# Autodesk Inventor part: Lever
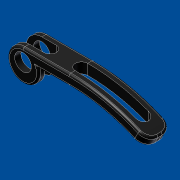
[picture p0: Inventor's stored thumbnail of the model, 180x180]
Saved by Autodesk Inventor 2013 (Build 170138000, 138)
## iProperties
Shininess: 41.0
Length Units: 11269
Angle Units: 11279
Time Units: 11290
Mass Units: 11283
Length Display Precision: 3
Angle Display Precision: 2
Created: 2001-04
Part Number: Lever
Material: Standard
Document SubType Name: Modellieren
Designer: dl
Density: 1 g/cm^3
Density: 0.0
Volumn: 0.0
Area: 0.0
PropertySet Name: Model Information
Control State: 0
Master: False
Checked Out: False
Author: dl
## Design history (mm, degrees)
sketch "Sketch1"
  geometry: L1 (-62.431, -13.947)-(-40.431, -13.947); L2 (-55.36, -18.947)-(-40.431, -18.947); L3 (-2.431, -23.212)-(-40.431, -96.502); A1 r 7.5 centre (-62.431, -21.447) between (-62.431, -13.947) and (-55.36, -18.947); A2 r 82.556 centre (-40.431, -96.502) between (-2.431, -23.212) and (-40.431, -13.947); A3 r 77.556 centre (-40.431, -96.502) between (-4.733, -27.651) and (-40.431, -18.947)
  constraints: 7 end point, 6 point on circle, 3 centre point, 3 tangent, 1 concentric, 1 horizontal, 1 parallel, 1 point on line
  dimensions: "d0" = 7.5 radius of A1; "d3" = 22 distance of L1.start L1.end; "d4" = 60 horizontal distance of L3.start A1.centre; "d5" = 5 distance of A3.start L3.start
extrude "Extrusion1" new body sketch "Sketch1" distance "d6" = 12; taper "d7" = 0 deg
sketch "Sketch2"
  geometry: L1 (0, 0)-(0, -12) reference; L2 (-10, -3)-(10, -3); L3 (10, -3)-(10, -9); L4 (10, -9)-(-10, -9); L5 (-10, -9)-(-10, -3); L6 (7.5, -16)-(-7.5, -12) reference; L7 (0, 0)-(0, -12)
  constraints: 10 end point, 3 equal length, 1 horizontal, 1 perpendicular
  dimensions: "d8" = 6 distance of L4.end L2.start; "d9" = 3 distance between parallel lines of L6 L4; "d10" = 10 distance from line of L2.end L1; "d11" = 20 distance of L2.start L2.end
extrude "Extrusion2" cut sketch "Sketch2" distance "d12" = 30; taper "d13" = 0 deg
sketch "Sketch3"
  geometry: L1 (54, -9)-(19, -9); L2 (19, -9)-(19, -3); L3 (19, -3)-(54, -3); L4 (54, -3)-(54, -9); L5 (7.5, 0)-(-7.5, 0) reference; A1 r 3 centre (7, -6) between (7, -9) and (7, -3) reference
  constraints: 8 end point, 2 parallel, 1 horizontal, 1 perpendicular
  dimensions: "d15" = 6 distance of L1.end L2.end; "d16" = 3 distance between parallel lines of L5 L3; "d17" = 12 distance from line of A1.centre L2; "d18" = 35 distance of L1.start L1.end
extrude "Extrusion3" cut sketch "Sketch3" stored distance "d19" = 30; taper "d20" = 0 deg
body "Solid1"
fillet "Fillet1" dims "d14" = 3
fillet "Fillet2" dims "d21" = 3
fillet "Fillet3" dims "d22" = 5
sketch "Sketch4"
  geometry: A1 r 7.5 centre (62.431, -21.447) between (55.36, -18.947) and (62.431, -13.947) reference; 1 further point
  dimensions: "d23" = 0 horizontal distance of A1.centre point (62.431, -19.947); "d24" = 1.5 distance of A1.centre point (62.431, -19.947)
hole "Hole1" sketch "Sketch4" diameter "d25" = 8; stored, may be unused: countersink angle "d29" = 60 deg, drill point angle "d31" = 118 deg; dims "d26" = 6, "d27" = 4, "d28" = 2, "d30" = 8
fillet "Fillet4" dims "d32" = 1
